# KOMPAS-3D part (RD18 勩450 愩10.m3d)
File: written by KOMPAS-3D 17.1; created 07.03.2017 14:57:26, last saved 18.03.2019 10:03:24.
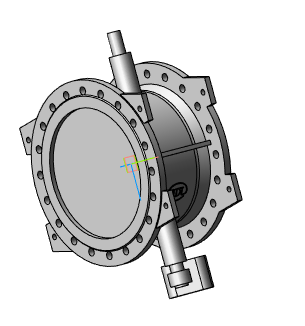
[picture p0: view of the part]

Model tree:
1. Операция без истории:2  (labels: Сталь 20  ГОСТ 1050-88)

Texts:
  RD18 Ду100 Ру16
  RD18 Ду150 Ру16
  RD18 Ду200 Ру16
  RD18 Ду250 Ру16
  RD18 Ду300 Ру16
  RD18 Ду350 Ру16
  RD18 Ду400 Ру10
  RD18 Ду400 Ру16
  RD18 Ду450 Ру10
  RD18 Ду450 Ру16
  RD18 Ду500 Ру10
  RD18 Ду500 Ру16
  RD18 Ду600 Ру10
  RD18 Ду600 Ру16
  RD18 Ду700 Ру10
  RD18 Ду700 Ру16
  RD18 Ду800 Ру10
  RD18 Ду800 Ру16
  RD18 Ду900 Ру10
  RD18 Ду900 Ру16
  RD18 Ду1000 Ру10
  RD18 Ду1000 Ру16
  RD18 Ду1200 Ру16
  RD18 Ду1400 Ру16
